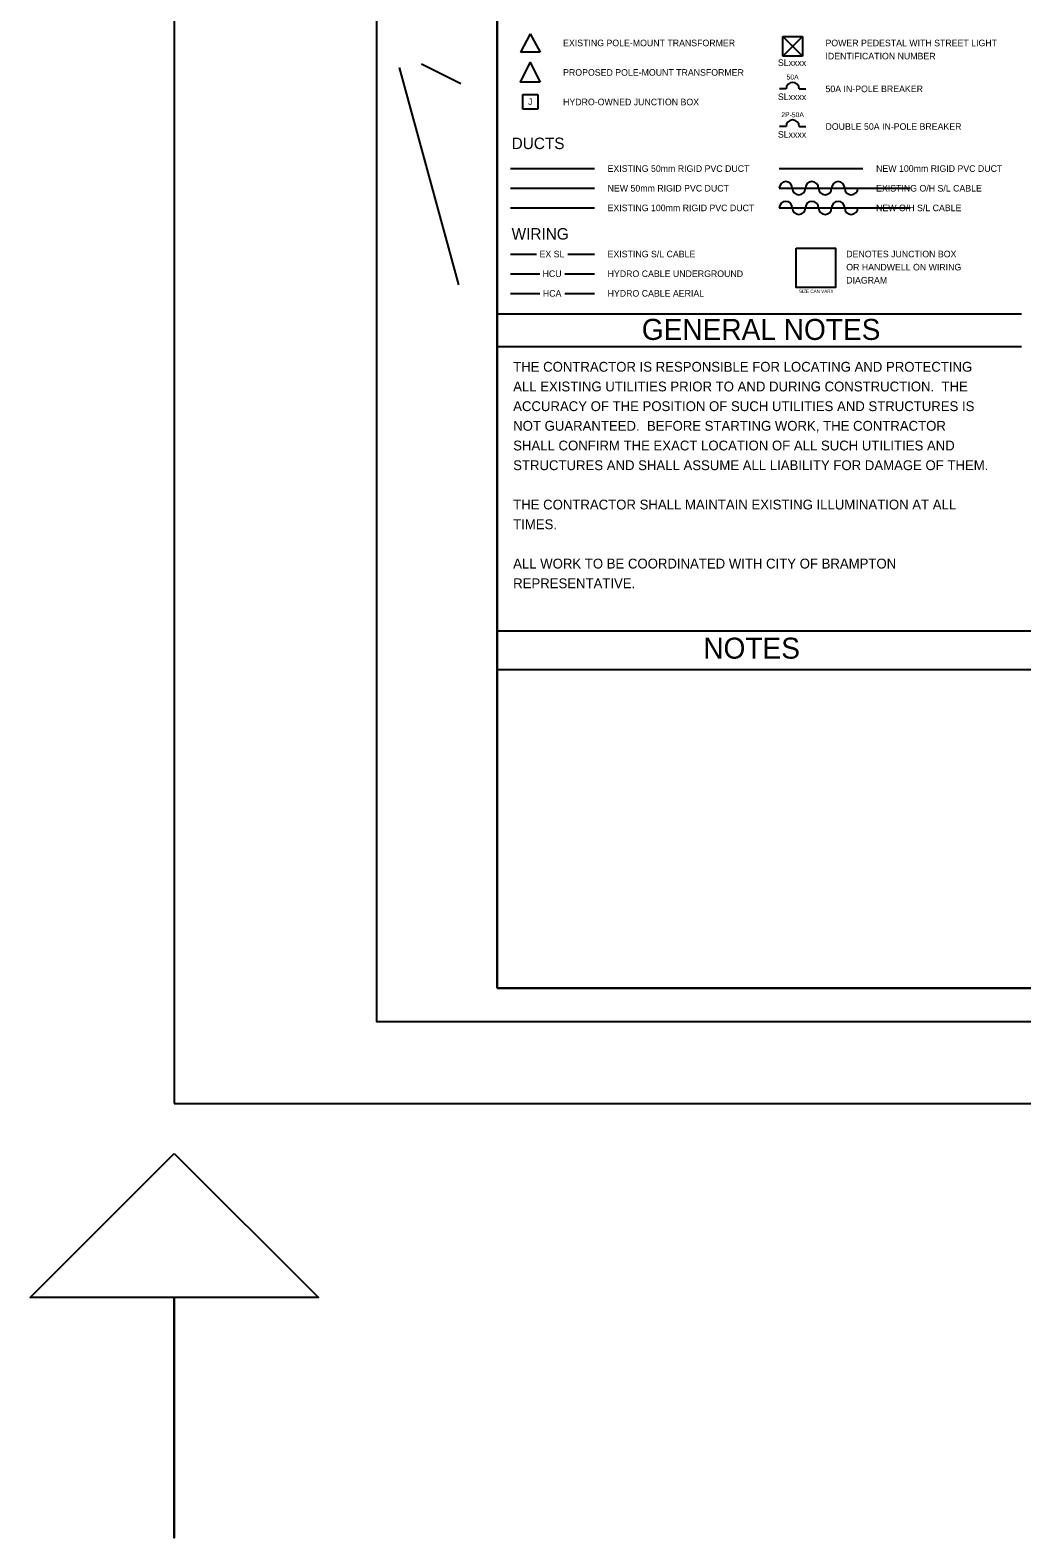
# Model space of a CAD drawing. Extents: x 602909 to 603631, y 4846273 to 4846729.
# Drawn here: x 602908.8 to 603054.8, y 4846276.7 to 4846498.6 of the extents above; entities that cross this region are included whole.
import ezdxf

# ---------------------------------------------------------------- set-up
doc = ezdxf.new("R2010")
doc.units = 0
for name, color, linetype in [('-PRINT FULLSIZE', 7, 'Continuous'), ('-PRINT HALFSIZE', 7, 'Continuous'), ('ENG_BORDER', 7, 'Continuous'), ('ENG_TX_TITLEBLOCK', 7, 'Continuous'), ('ENG_WK_MISC-1', 7, 'Continuous'), ('SL - Border Text', 7, 'Continuous'), ('STL_CONDUCTORS_OH', 7, 'Continuous'), ('STL_CONDUIT_UG_100mm', 7, 'Continuous'), ('STL_CONDUIT_UG_50mm', 7, 'Continuous'), ('STL_EXIST_CONDUIT_UG_100mm', 7, 'Continuous'), ('STL_EXIST_CONDUIT_UG_50mm', 7, 'Continuous'), ('STL_EXISTING_CONDUCTORS_OH', 7, 'Continuous'), ('STL_EXISTING_TRANSFORMERS', 7, 'Continuous'), ('STL_POWER_SUPPLY', 7, 'Continuous'), ('STL_TRANSFORMERS', 7, 'Continuous'), ('STL_WIRING', 7, 'Continuous')]:
    doc.layers.add(name, color=color, linetype=linetype)

msp = doc.modelspace()

# ---------------------------------------------------------------- linework, layer by layer
at = {"layer": '-PRINT FULLSIZE'}
msp.add_lwpolyline([(602930, 4846340.65), (603377.03, 4846340.65), (603377.03, 4846645.65), (602930, 4846645.65)], close=True, dxfattribs=at)
at = {"layer": '-PRINT HALFSIZE'}
msp.add_lwpolyline([(602959.8, 4846631.64), (603368.72, 4846631.64), (603368.72, 4846352.64), (602959.8, 4846352.64)], close=True, dxfattribs=at)
at = {"layer": 'ENG_BORDER'}
for p, q in [((602977.52, 4846357.64), (602977.52, 4846626.85)), ((602977.52, 4846456.89), (603054.73, 4846456.89)), ((602977.52, 4846452.07), (603054.73, 4846452.07)), ((602977.52, 4846410.23), (603363.74, 4846410.23)), ((602977.52, 4846404.5), (603194.76, 4846404.5)), ((603363.72, 4846357.64), (602977.52, 4846357.64))]:
    msp.add_line(p, q, dxfattribs=at)
msp.add_lwpolyline([(602977.52, 4846357.64), (603363.72, 4846357.64), (603363.72, 4846626.64), (602977.52, 4846626.64)], close=True, dxfattribs=at)
at = {"layer": 'ENG_WK_MISC-1'}
msp.add_lwpolyline([(602930, 4846333.27), (602951.22, 4846312.06), (602930, 4846312.06), (602930, 4846276.7), (602930, 4846312.06), (602908.79, 4846312.06)], close=True, dxfattribs=at)
at = {"layer": 'SL - Border Text'}
for p, q in [((602963.09, 4846493.16), (602971.84, 4846461.16)), ((602966.42, 4846493.68), (602972.18, 4846490.8)), ((603019.04, 4846475.37), (603038.35, 4846475.37)), ((603019.04, 4846472.47), (603038.35, 4846472.47))]:
    msp.add_line(p, q, dxfattribs=at)
at = {"layer": 'STL_CONDUCTORS_OH'}
for centre, start, end in [((603020.01, 4846472.47), 0, 180), ((603023.87, 4846472.47), 0, 180), ((603027.73, 4846472.47), 0, 180), ((603021.94, 4846472.47), 180, 0), ((603025.8, 4846472.47), 180, 0), ((603029.66, 4846472.47), 180, 0)]:
    msp.add_arc(centre, 0.965, start, end, dxfattribs=at)
at = {"layer": 'STL_CONDUIT_UG_100mm'}
msp.add_line((603019.04, 4846478.26), (603031.38, 4846478.26), dxfattribs=at)
at = {"layer": 'STL_CONDUIT_UG_50mm'}
msp.add_line((602979.52, 4846475.37), (602991.85, 4846475.37), dxfattribs=at)
at = {"layer": 'STL_EXIST_CONDUIT_UG_100mm'}
msp.add_line((602979.52, 4846472.47), (602991.85, 4846472.47), dxfattribs=at)
at = {"layer": 'STL_EXIST_CONDUIT_UG_50mm'}
msp.add_line((602979.52, 4846478.26), (602991.85, 4846478.26), dxfattribs=at)
at = {"layer": 'STL_EXISTING_CONDUCTORS_OH'}
for centre, start, end in [((603020.01, 4846475.37), 0, 180), ((603021.94, 4846475.37), 180, 0), ((603023.87, 4846475.37), 0, 180), ((603025.8, 4846475.37), 180, 0), ((603027.73, 4846475.37), 0, 180), ((603029.66, 4846475.37), 180, 0)]:
    msp.add_arc(centre, 0.965, start, end, dxfattribs=at)
at = {"layer": 'STL_EXISTING_TRANSFORMERS'}
for p, q in [((602982.41, 4846498.12), (602980.97, 4846495.38)), ((602982.41, 4846498.12), (602983.86, 4846495.38)), ((602983.86, 4846495.38), (602980.97, 4846495.38)), ((602981.33, 4846487.01), (602981.33, 4846489.18)), ((602981.33, 4846489.18), (602983.5, 4846489.18)), ((602983.5, 4846489.18), (602983.5, 4846487.01)), ((602983.5, 4846487.01), (602981.33, 4846487.01))]:
    msp.add_line(p, q, dxfattribs=at)
at = {"layer": 'STL_POWER_SUPPLY'}
for p, q in [((603019.59, 4846494.82), (603019.59, 4846497.72)), ((603019.59, 4846497.72), (603022.48, 4846497.72)), ((603019.59, 4846497.72), (603022.48, 4846494.82)), ((603022.48, 4846497.72), (603019.59, 4846494.82)), ((603021.03, 4846497.72), (603022.48, 4846497.72)), ((603022.48, 4846497.72), (603022.48, 4846494.82)), ((603022.48, 4846494.82), (603019.59, 4846494.82)), ((603020.07, 4846489.99), (603019.1, 4846489.99)), ((603022, 4846489.99), (603022.96, 4846489.99)), ((603020.07, 4846484.45), (603019.1, 4846484.45)), ((603022, 4846484.45), (603022.96, 4846484.45))]:
    msp.add_line(p, q, dxfattribs=at)
for centre in [(603021.03, 4846489.99), (603021.03, 4846484.45)]:
    msp.add_arc(centre, 0.965, 0, 180, dxfattribs=at)
at = {"layer": 'STL_TRANSFORMERS'}
msp.add_lwpolyline([(602983.86, 4846490.96), (602980.97, 4846490.96), (602982.41, 4846493.86), (602982.41, 4846493.86)], close=True, dxfattribs=at)
at = {"layer": 'STL_WIRING'}
for p, q in [((602979.52, 4846465.68), (602983.31, 4846465.68)), ((602987.94, 4846465.68), (602991.85, 4846465.68)), ((602979.52, 4846462.78), (602983.81, 4846462.78)), ((602987.49, 4846462.78), (602991.85, 4846462.78)), ((602979.52, 4846459.89), (602983.82, 4846459.89)), ((602987.48, 4846459.89), (602991.85, 4846459.89))]:
    msp.add_line(p, q, dxfattribs=at)
msp.add_lwpolyline([(603021.53, 4846466.56), (603027.32, 4846466.56), (603027.32, 4846460.76), (603021.53, 4846460.76)], close=True, dxfattribs=at)

# ---------------------------------------------------------------- texts
at = {"layer": 'ENG_TX_TITLEBLOCK'}
for s, height, rotation, p in [('EXISTING POLE-MOUNT TRANSFORMER', 0.9655, 359.9999, (602987.24, 4846496.27)), ('POWER PEDESTAL WITH STREET LIGHT ', 0.9655, 359.9999, (603025.86, 4846496.27)), ('IDENTIFICATION NUMBER', 0.9655, 359.9999, (603025.86, 4846494.34)), ('PROPOSED POLE-MOUNT TRANSFORMER', 0.9655, 359.9999, (602987.24, 4846491.93)), ('50A IN-POLE BREAKER', 0.9655, 359.9999, (603025.86, 4846489.51)), ('HYDRO-OWNED JUNCTION BOX', 0.9655, 359.9999, (602987.24, 4846487.58)), ('DOUBLE 50A IN-POLE BREAKER', 0.9655, 359.9999, (603025.86, 4846483.97)), ('DUCTS', 1.69, 360, (602979.66, 4846481.13)), ('EXISTING 50mm RIGID PVC DUCT', 0.9655, 359.9999, (602993.79, 4846477.78)), ('NEW 100mm RIGID PVC DUCT', 0.9655, 359.9999, (603033.31, 4846477.78)), ('NEW 50mm RIGID PVC DUCT', 0.9655, 359.9999, (602993.79, 4846474.88)), ('EXISTING O/H S/L CABLE', 0.9655, 359.9999, (603033.31, 4846474.88)), ('EXISTING 100mm RIGID PVC DUCT', 0.9655, 359.9999, (602993.79, 4846471.99)), ('NEW O/H S/L CABLE', 0.9655, 359.9999, (603033.31, 4846471.99)), ('WIRING', 1.69, 360, (602979.66, 4846467.81)), ('EXISTING S/L CABLE', 0.9655, 359.9999, (602993.79, 4846465.2)), ('DENOTES JUNCTION BOX', 0.9655, 359.9999, (603028.92, 4846465.2)), ('OR HANDWELL ON WIRING ', 0.9655, 359.9999, (603028.92, 4846463.27)), ('HYDRO CABLE UNDERGROUND', 0.9655, 359.9999, (602993.79, 4846462.3)), ('DIAGRAM', 0.965, 359.9999, (603028.92, 4846461.34)), ('HYDRO CABLE AERIAL', 0.9655, 359.9999, (602993.79, 4846459.41)), ('NOTES', 3.09, 360, (603007.87, 4846406.12))]:
    msp.add_text(s, height=height, rotation=rotation, dxfattribs=at).set_placement(p)
for s, height, p in [('THE CONTRACTOR IS RESPONSIBLE FOR LOCATING AND PROTECTING', 1.4482, (602979.89, 4846448.36)), ('ALL EXISTING UTILITIES PRIOR TO AND DURING CONSTRUCTION.  THE ', 1.4482, (602979.89, 4846445.46)), ('ACCURACY OF THE POSITION OF SUCH UTILITIES AND STRUCTURES IS ', 1.4482, (602979.89, 4846442.56)), ('NOT GUARANTEED.  BEFORE STARTING WORK, THE CONTRACTOR ', 1.4482, (602979.89, 4846439.67)), ('SHALL CONFIRM THE EXACT LOCATION OF ALL SUCH UTILITIES AND ', 1.4482, (602979.89, 4846436.77)), ('STRUCTURES AND SHALL ASSUME ALL LIABILITY FOR DAMAGE OF THEM.   ', 1.4482, (602979.89, 4846433.87)), ('THE CONTRACTOR SHALL MAINTAIN EXISTING ILLUMINATION AT ALL ', 1.4482, (602979.89, 4846428.08)), ('TIMES.', 1.448, (602979.89, 4846425.18)), ('ALL WORK TO BE COORDINATED WITH CITY OF BRAMPTON ', 1.4482, (602979.89, 4846419.39)), ('REPRESENTATIVE.', 1.4482, (602979.89, 4846416.49))]:
    msp.add_text(s, height=height, dxfattribs=at).set_placement(p)
at = {"layer": 'SL - Border Text'}
for s, height, rotation, p in [('SIZE CAN VARY', 0.4827, 359.9999, (603021.97, 4846459.96)), ('GENERAL NOTES', 3.0896, 360, (602998.82, 4846453.04))]:
    msp.add_text(s, height=height, rotation=rotation, dxfattribs=at).set_placement(p)
at = {"layer": 'STL_EXISTING_TRANSFORMERS'}
msp.add_text('J', height=0.965, rotation=359.9999, dxfattribs=at).set_placement((602982.08, 4846487.62))
at = {"layer": 'STL_POWER_SUPPLY'}
for p in [(603018.86, 4846493.37), (603018.86, 4846488.35), (603018.86, 4846482.81)]:
    msp.add_text('SLxxxx', height=0.965, rotation=359.9999, dxfattribs=at).set_placement(p)
for s, p in [('50A', (603020.13, 4846491.37)), ('2P-50A', (603019.35, 4846485.83))]:
    msp.add_text(s, height=0.724, dxfattribs=at).set_placement(p)
at = {"layer": 'STL_WIRING'}
for s, p in [('EX SL', (602983.77, 4846465.2)), ('HCU', (602984.22, 4846462.3)), ('HCA', (602984.26, 4846459.41))]:
    msp.add_text(s, height=0.965, dxfattribs=at).set_placement(p)

doc.saveas('drawing.dxf')
